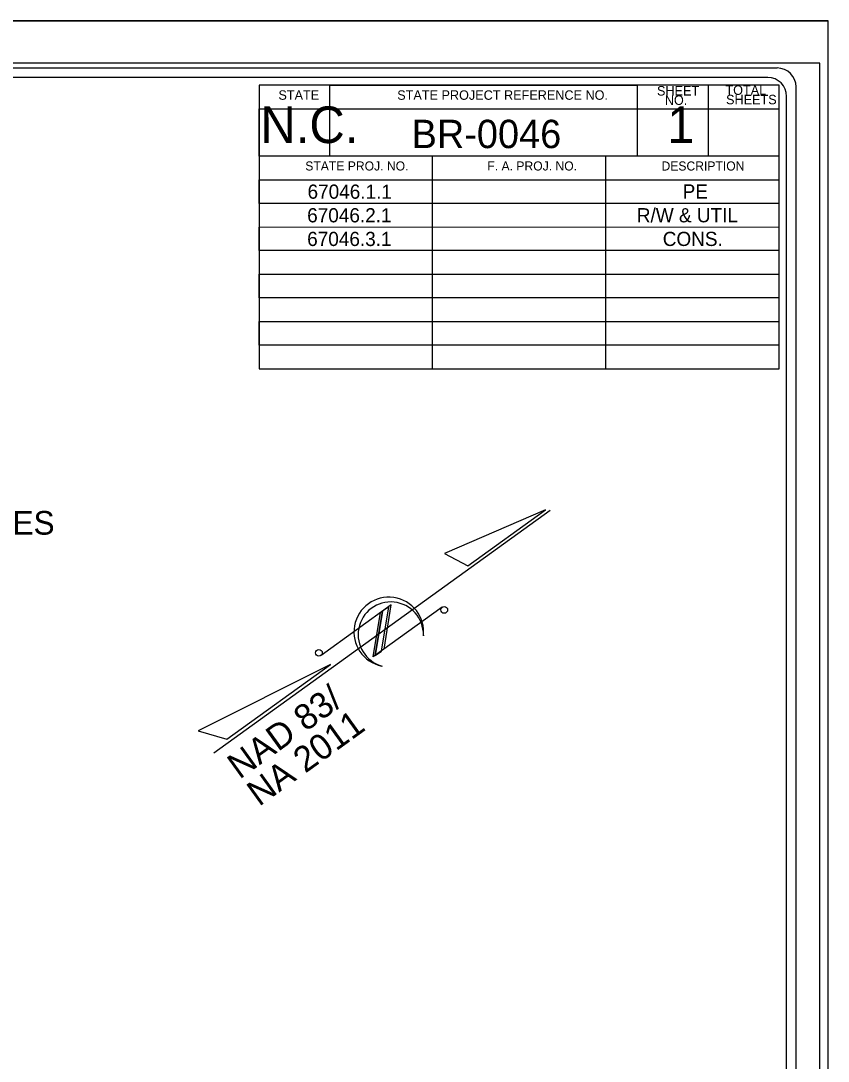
# Model space of a CAD drawing. Extents: x 2163579 to 2286010, y 210234 to 425257.
# Drawn here: x 2244027 to 2271355, y 366236 to 401435 of the extents above; entities that cross this region are included whole.
import ezdxf

# ---------------------------------------------------------------- set-up
doc = ezdxf.new("R2010")
doc.units = 0
for name, color, linetype in [('Sheet Cutting Line CELL', 7, 'Continuous'), ('Sheet Data Field CELL', 7, 'Continuous'), ('Sheet North Arrow CELL', 7, 'Continuous'), ('Sheet Plot Border Inside CELL', 7, 'Continuous'), ('Sheet Plot Border Outside CELL', 7, 'Continuous'), ('Sheet Title CELL', 7, 'Continuous')]:
    doc.layers.add(name, color=color, linetype=linetype)

msp = doc.modelspace()

# ---------------------------------------------------------------- linework, layer by layer
at = {"layer": 'Sheet Cutting Line CELL'}
msp.add_line((2163579, 401435), (2271355, 401435), dxfattribs=at)
at = {"layer": 'Sheet North Arrow CELL'}
for p, q in [((2250559, 376674), (2261949, 384883)), ((2256564, 381674), (2254188, 379961)), ((2258294, 381597), (2255957, 379912)), ((2256235, 380113), (2256479, 381612)), ((2256479, 381612), (2256265, 381458)), ((2256321, 380175), (2256564, 381674)), ((2255957, 379912), (2256200, 381411)), ((2256022, 379959), (2256265, 381458)), ((2256265, 381458), (2256022, 379959)), ((2257656, 380647), (2257656, 380628)), ((2256022, 379959), (2256235, 380113))]:
    msp.add_line(p, q, dxfattribs=at)
for points in [[(2261792, 384890), (2258365, 383408), (2259163, 382996)], [(2254505, 379659), (2250027, 377412), (2251000, 377133)]]:
    msp.add_lwpolyline(points, close=True, dxfattribs=at)
for centre in [(2258360, 381503), (2254118, 380051)]:
    msp.add_circle(centre, 114, dxfattribs=at)
for centre, radius, start, end in [((2256483, 380760), 1179, 353.6224, 258.1764), ((2256550, 380668), 1106, 358.8774, 254.4111)]:
    msp.add_arc(centre, radius, start, end, dxfattribs=at)
at = {"layer": 'Sheet Plot Border Inside CELL'}
msp.add_lwpolyline([(2164411, 332472), (2271067, 332472), (2271067, 399999), (2164411, 399999)], close=True, dxfattribs=at)
at = {"layer": 'Sheet Plot Border Outside CELL'}
msp.add_lwpolyline([(2271355, 401435), (2163579, 401435), (2163579, 331036), (2271355, 331036)], close=True, dxfattribs=at)
at = {"layer": 'Sheet Title CELL'}
for points in [[(2269628, 399835), (2174906, 399836)], [(2269307, 399515), (2178428, 399515)], [(2252091, 389660), (2269691, 389660), (2269691, 390459), (2252091, 390460), (2252091, 391259), (2269691, 391259), (2269691, 392059), (2252092, 392059), (2252091, 392860), (2269691, 392860), (2269691, 393660), (2252091, 393660), (2252091, 394459), (2269691, 394460), (2269691, 395259), (2252091, 395259), (2252091, 396059), (2269691, 396059), (2269691, 396860), (2252091, 396860), (2252091, 398460), (2269691, 398460), (2269691, 399260), (2252091, 399259), (2252091, 389660), (2257957, 389659), (2257957, 396859), (2254491, 396859), (2254491, 399260), (2264892, 399259), (2264891, 396860), (2263822, 396860), (2263822, 389660), (2269691, 389660), (2269691, 399260), (2267291, 399260), (2267292, 396860)], [(2270267, 333276), (2270267, 399195)], [(2269947, 345435), (2269947, 398876)]]:
    msp.add_lwpolyline(points, dxfattribs=at)
for centre in [(2269307, 398879), (2269627, 399199)]:
    msp.add_arc(centre, 640, 0, 90, dxfattribs=at)

# ---------------------------------------------------------------- texts
at = {"layer": 'Sheet Data Field CELL'}
for s, height, p in [('BR-0046', 960, (2257253, 397128)), ('67046.1.1', 480, (2253733, 395416)), ('PE', 480, (2266428, 395423))]:
    msp.add_text(s, height=height, rotation=360, dxfattribs=at).set_placement(p)
for s, height, p in [('67046.2.1', 480, (2253720, 394616)), ('R/W & UTIL', 480, (2264878, 394617)), ('67046.3.1', 480, (2253720, 393816)), ('CONS.', 480, (2265755, 393817)), ('GRADING, PAVING, DRAINAGE AND STRUCTURES', 800.01, (2219196, 384051))]:
    msp.add_text(s, height=height, dxfattribs=at).set_placement(p)
at = {"layer": 'Sheet North Arrow CELL'}
for s, p in [('NAD 83/', (2251430, 375754)), ('NA 2011', (2252092, 374835))]:
    msp.add_text(s, height=864, rotation=35.7823, dxfattribs=at).set_placement(p)
at = {"layer": 'Sheet Title CELL'}
for s, height, p in [('SHEET', 320, (2265560, 398907)), ('TOTAL', 320, (2267877, 398931)), ('STATE', 320, (2252747, 398764)), ('STATE PROJECT REFERENCE NO.', 319.99, (2256769, 398763)), ('NO.', 320, (2265825, 398591)), ('SHEETS', 320, (2267898, 398611)), ('N.C.', 1238.4, (2252139, 397299)), ('1', 1238, (2265905, 397299)), ('STATE PROJ. NO.', 307.2, (2253656, 396371)), ('F. A. PROJ. NO.', 307.2, (2259819, 396371)), ('DESCRIPTION', 307.2, (2265713, 396370))]:
    msp.add_text(s, height=height, rotation=360, dxfattribs=at).set_placement(p)

doc.saveas('drawing.dxf')
